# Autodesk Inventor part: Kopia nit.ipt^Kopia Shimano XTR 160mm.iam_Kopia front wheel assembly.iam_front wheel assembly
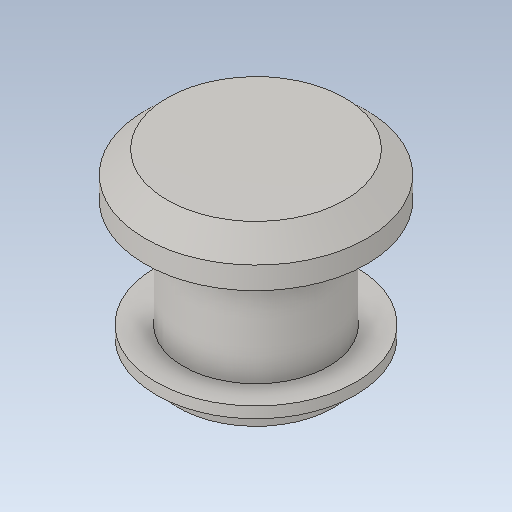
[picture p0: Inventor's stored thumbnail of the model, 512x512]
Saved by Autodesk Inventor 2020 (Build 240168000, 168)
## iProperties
Created: 2017-09
Part Number: Kopia nit.ipt^Kopia Shimano XTR 160mm.iam_Kopia front wheel assembly.iam_front wheel assembly
Material: Ogólny
Document SubType Name: Modeling
Designer: Tomasz
Density: 1 g/cm^3
Appearance: Domyślna
Sending System: SolidWorks 2017
Last Author: Tomasz
Last Saved: 2017-09-11
Author: Tomasz
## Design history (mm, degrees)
feature "nit.ipt"
node "Bryła1"
